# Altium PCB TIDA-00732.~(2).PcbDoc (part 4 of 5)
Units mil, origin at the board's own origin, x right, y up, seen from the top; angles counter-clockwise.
Board outline 8994.78 x 4186 mil, 6 copper layers (Top Layer, GND1, PWR1, PWR2, GND2, Bottom Layer), stack 97.668 mil thick; 693 components, 463 nets, 2087 pads, 616 vias.
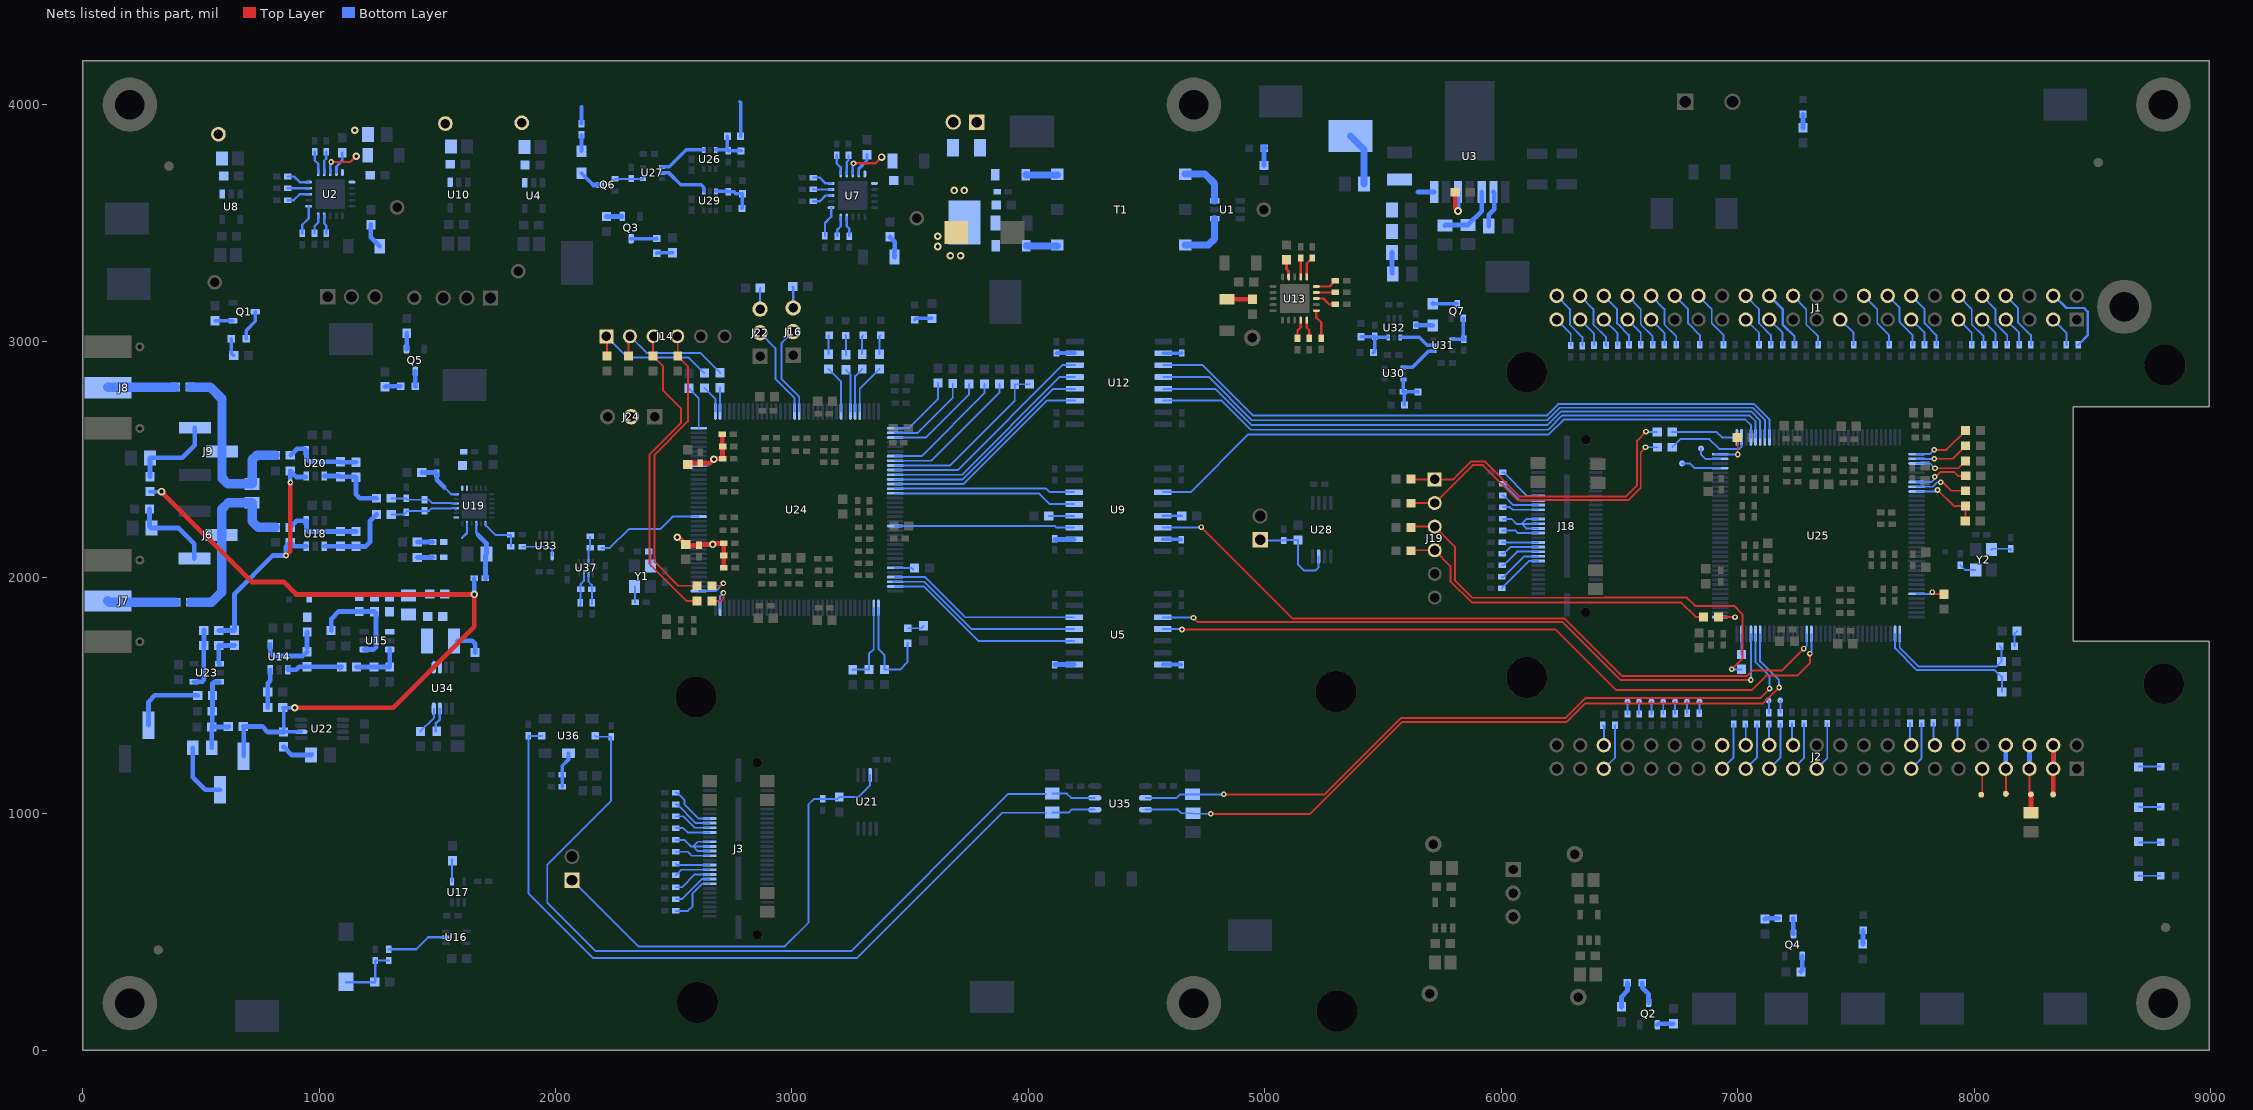
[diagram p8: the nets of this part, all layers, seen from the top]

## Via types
v1: diameter 32, hole 16, Top Layer to Bottom Layer, tented both sides, 393 vias
v2: diameter 24, hole 12, Top Layer to Bottom Layer, tented both sides, 174 vias
v3: diameter 19.68, hole 7.87, Top Layer to Bottom Layer, tented both sides, 20 vias
v4: diameter 40, hole 20, Top Layer to Bottom Layer, tented both sides, 19 vias
v5: diameter 36, hole 16, Top Layer to Bottom Layer, tented both sides, 9 vias
v6: diameter 24, hole 12, Top Layer to Bottom Layer, 1 vias

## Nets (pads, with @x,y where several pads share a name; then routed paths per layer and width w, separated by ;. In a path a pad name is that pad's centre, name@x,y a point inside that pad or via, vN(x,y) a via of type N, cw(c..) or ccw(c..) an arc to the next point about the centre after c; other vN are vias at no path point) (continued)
GPIO_38: J1.3 R1.2 | length 130.6
  Bottom Layer w8: J1.3@8334,3091 8390,3035 R1.2@8390,2983.62
GPIO_39: J1.4 R2.1 | length 330.7
  Bottom Layer w10: J1.4@8334,3191 8339,3191 8390,3140 8464.01,3140 8480,3124.01 8480,3023.62 R2.1@8440,2983.62
GPIO_46: J1.16 R14.1 | length 251.3
  Bottom Layer w8: J1.16@7734,3191 7790,3135 7790,3075 7840,3025 R14.1@7840,2983.62
GPIO_47: J1.15 R13.2 | length 130.6
  Bottom Layer w8: J1.15@7734,3091 7790,3035 R13.2@7790,2983.62
GPIO_48: J2.15 R127.2 | length 210.4
  Bottom Layer w8: J2.15@7734,1191 7777.5,1234.5 R127.2@7777.5,1383.38
GPIO_49: J2.23 R135.2 | length 209.8
  Bottom Layer w8: J2.23@7334,1191 7378.5,1235.5 R135.2@7378.5,1382.38
GPIO_50: J2.14 R126.1 | length 97.1
  Bottom Layer w8: R126.1@7827.5,1385.38 7827.5,1297.5 J2.14@7834,1291
GPIO_51: J2.16 R128.1 | length 95.7
  Bottom Layer w8: R128.1@7728.5,1384.38 7728.5,1296.5 J2.16@7734,1291
GPIO_60: J2.12 R124.1 | length 96.2
  Bottom Layer w8: R124.1@7929.5,1385.38 7929.5,1295.5 J2.12@7934,1291
GPIO_61: J1.26 R24.1 | length 251.3
  Bottom Layer w8: J1.26@7234,3191 7290,3135 7290,3070 7340,3020 R24.1@7340,2983.62
GPIO_65: J1.18 R16.1 | length 251.3
  Bottom Layer w8: J1.18@7634,3191 7685,3140 7685,3080 7740,3025 R16.1@7740,2983.62
GPIO_66: J1.7 R5.2 | length 130.6
  Bottom Layer w8: J1.7@8134,3091 8190,3035 R5.2@8190,2983.62
GPIO_67: J1.8 R6.1 | length 251.3
  Bottom Layer w8: J1.8@8134,3191 8185,3140 8185,3080 8240,3025 R6.1@8240,2983.62
GPIO_68: J1.10 R8.1 | length 251.3
  Bottom Layer w8: J1.10@8034,3191 8090,3135 8090,3075 8140,3025 R8.1@8140,2983.62
GPIO_69: J1.9 R7.2 | length 130.6
  Bottom Layer w8: J1.9@8034,3091 8090,3035 R7.2@8090,2983.62
GPIO_78: J1.37 R35.2 | length 130.6
  Bottom Layer w8: J1.37@6634,3091 6690,3035 R35.2@6690,2983.62
GPIO_79: J1.38 R36.1 | length 251.3
  Bottom Layer w8: J1.38@6634,3191 6690,3135 6690,3070 6740,3020 R36.1@6740,2983.62
GPIO_80: J1.36 R34.1 | length 251.3
  Bottom Layer w8: J1.36@6734,3191 6790,3135 6790,3075 6840,3025 R34.1@6840,2983.62
GPIO_81: J1.34 R32.1 | length 251.3
  Bottom Layer w8: J1.34@6834,3191 6890,3135 6890,3075 6940,3025 R32.1@6940,2983.62
ISO_ADC_CONVST: U5.12 U24.71 | length 853
  Bottom Layer w8: U24.71@3436.35,1962.2 3557.8,1962.2 3788.01,1731.99 U5.12@4194,1731.99
ISO_ADC_CSN: U9.13 U24.51 | length 776.2
  Bottom Layer w8: U24.51@3436.35,2355.9 4044.1,2355.9 4089.02,2310.98 U9.13@4193.99,2310.98
ISO_ADC_RESETN: U5.14 U24.69 | length 827.9
  Bottom Layer w8: U24.69@3436.35,2001.57 3563.43,2001.57 3733.01,1831.99 U5.14@4194,1831.99
ISO_ADC_RVS: U9.11 U24.58 | length 760.6
  Bottom Layer w8: U24.58@3436.35,2218.1 4110.9,2218.1 4118.02,2210.98 U9.11@4193.99,2210.98
ISO_ADC_SCLK: U5.13 U24.70 | length 859.1
  Bottom Layer w8: U24.70@3436.35,1979.8 3429.53,1979.8 3427.45,1981.88 U24.70@3436.35,1981.88 3560.32,1981.88 3760.21,1781.99 U5.13@4194,1781.99
ISO_ADC_SDI: U9.14 U24.50 | length 763.7
  Bottom Layer w8: U24.50@3436.35,2375.58 4075.4,2375.58 4090,2360.98 U9.14@4193.99,2360.98
ISO_ADC_SDO0: U12.6 U24.46 | length 944.4
  Bottom Layer w8: U24.46@3436.35,2454.32 3700.32,2454.32 4144,2898 U12.6@4196.99,2898
ISO_ADC_SDO1: U12.3 U24.49 | length 906.7
  Bottom Layer w8: U24.49@3436.35,2395.27 3724.88,2395.27 4077.61,2748 U12.3@4196.99,2748
ISO_ADC_SDO2: U12.4 U24.48 | length 919.3
  Bottom Layer w8: U24.48@3436.35,2414.95 3722.36,2414.95 4105.41,2798 U12.4@4196.99,2798
ISO_ADC_SDO3: U12.5 U24.47 | length 931.9
  Bottom Layer w8: U24.47@3436.35,2434.64 3719.84,2434.64 4133.2,2848 U12.5@4196.99,2848
ISO_SCL: R206.1 R271.1 U35.6 U36.8 | length 3465.5
  Bottom Layer w8: R271.1@1885,1331.38 1885,665 2160,390 3275,390 3890,1005 R206.1@4075,1005 ; R271.1@1886.38,1330 U36.8@1942.2,1330 ; R206.1@4101,1006 4170,1006 4182,1018 U35.6@4280.72,1018
ISO_SDA: R204.1 R270.1 U35.7 U36.7 | length 3539.5
  Bottom Layer w8: U36.7@2167.8,1330 2171.42,1326.38 R270.1@2235,1326.38 2235,1055 1965,785 1965,625 2170,420 3250,420 3915,1085 R204.1@4075,1085 ; R204.1@4101,1086 4163,1086 4181,1068 U35.7@4280.72,1068
LDO_EN1: Q6.1 R250.2 U27.4 | length 118.2
  Bottom Layer w8: Q6.1@2251.5,3685.59 2321.79,3685.59 2321.97,3685.41 U27.4@2369.65,3685.41
LDO_EN2: Q7.1 R257.2 U31.4 | length 135.1
  Bottom Layer w15: U31.4@5794.35,3007.59 R257.2@5841,3007.62 ; R257.2@5839.59,3009.03 Q7.1@5839.59,3095.5
  Bottom Layer w20: R257.2@5839.59,3009.03 R257.2@5841,3007.62
LDO_IN_ISO: C4.1 C5.1 C7.1 C17.1 C18.1 C19.1 C20.1 C31.1 C32.1 C35.1 C36.1 J25.2 R51.2 R247.2 R248.2 TP8.1 TP13.1 TP14.1 U2.13 U2.15 U2.16 U4.1 U7.13 U7.15 U7.16 U8.1 U10.1 | length 566.2
  Top Layer w10: v2(1051,3757) 1132,3757 v1(1157,3782) ; v2(3260.66,3751.54) 3352.54,3751.54 v1(3379,3778)
  Top Layer w20: v1(1157,3782) v1@1160.92,3785.92
  Bottom Layer w10: U2.13@1047.52,3712.46 1047.52,3753.52 v2(1051,3757) ; U7.13@3257.18,3707 3257.18,3748.06 v2(3260.66,3751.54)
  Bottom Layer w15: R247.2@2110,3919.62 2110,3990 2111,3991 ; 2780,4012 2783,4009 R248.2@2783,3866
  Bottom Layer w20: v1(1151,3892) v1@1155,3892
MCLK: R273.2 U24.125 | length 466.9
  Bottom Layer w8: R273.2@2193.62,2125 2230,2125 2310,2205 2442.53,2205 2495,2257.47 U24.125@2605.65,2257.47
MODE_SW0: J16.2 U24.19 | length 389.8
  Bottom Layer w8: J16.2@3005,3040 2955,2990 2955,2840 3030.84,2764.16 U24.19@3030.84,2702.35
MODE_SW1: J22.2 U24.18 | length 393.2
  Bottom Layer w8: J22.2@2865,3035 2930,2970 2930,2840 3011.16,2758.84 U24.18@3011.16,2702.35
NetC1_1: C1.1 R46.1 | length 118
  Bottom Layer w20: C1.1@1585.88,1732.4 1647.6,1732.4 1660,1720 R46.1@1660,1682.5 R46.1@1659.09,1683.4
NetC2_1: C2.1 C3.2 C6.1 C237.1 D1.1 D3.1 J25.1 R51.1 TP3.1
  other v1: 3670,3361 3713,3361 3617,3400 3617,3443 3686,3637 3729,3637
NetC9_1: C9.1 R52.1 | length 107.2
  Bottom Layer w20: R52.1@1219,3492.5 1219,3438.93 C9.1@1256.93,3401
NetC10_2: C10.2 U2.14 | length 94.4
  Bottom Layer w12: U2.14@1073.11,3712.46 1073.11,3738.11 1098,3763 C10.2@1098,3796.5
NetC23_1: C23.1 R63.1 | length 94.5
  Bottom Layer w20: R63.1@3414,3440.5 3434.82,3419.68 3434.82,3390.39 3433.93,3389.5 C23.1@3433.93,3355
NetC24_2: C24.2 U7.14 | length 95.2
  Bottom Layer w12: U7.14@3282.77,3707 3282.77,3728.77 3317.18,3763.18 C24.2@3317.18,3787.97
NetC41_1: C41.1 U3.5 | length 164.1
  Top Layer w20: C41.1@5805.5,3629 5805.5,3563.5 5817,3552 v1(5817,3550)
  Bottom Layer w20: v1(5817,3550) U3.5@5817,3630.37
NetC42_1: C42.1 C91.1 L2.1 R220.2 TP32.1 U3.7 | length 296
  Bottom Layer w20: 5646.63,3630.37 U3.7@5717,3630.37
  Bottom Layer w30: TP32.1@5362,3867 5419,3810 L2.1@5419,3665
NetC47_1: C47.1 R76.1 | length 108.2
  Top Layer w15: C47.1@4839.25,3177.23 C47.1@4839.68,3176.8
  Top Layer w20: C47.1@4839.68,3176.8 R76.1@4947.25,3176.8
NetC48_2: C48.2 U13.14 | length 75.9
  Top Layer w12: C48.2@5091.25,3343.27 5091.25,3304.9 5100.66,3295.49 U13.14@5100.66,3271.3
NetC52_2: C52.2 R89.1 U15.1
NetC53_1: C53.1 R85.2 U14.3 | length 164
  Bottom Layer w20: R85.2@783.5,1450 C53.1@783.5,1515 783.5,1553.5 793.6,1563.6 U14.3@793.6,1609.87
NetC54_1: C54.1 R86.2 R88.2 U15.3 | length 214.9
  Bottom Layer w20: R86.2@1158.5,1622 1159,1621.5 R88.2@1233,1621.5 C54.1@1299,1621.5 1299.13,1621.63 U15.3@1299.13,1695.6
NetC56_1: C56.1 R87.1 R90.1 S1.2 | length 270
  Bottom Layer w10: S1.2@1114.33,289.43 1115.03,288.73 C56.1@1235.63,288.73 1238.13,291.23 R87.1@1238.13,380.11 R90.1@1294.13,380.11
NetC57_1: C57.1 R276.1 | length 64.9
  Bottom Layer w20: C57.1@1415.5,2085 R276.1@1480.38,2085
NetC58_1: C58.1 R268.1 | length 64.9
  Bottom Layer w20: C58.1@1415.5,2150 R268.1@1480.38,2150
NetC60_1: C60.1 R86.1 U14.1 | length 249.9
  Bottom Layer w20: U14.1@868.4,1619.4 U14.1@868.4,1609.87 904,1609.87 916.64,1622.5 C60.1@949,1622.5 949.5,1622 R86.1@1095.5,1622 R86.1@1090.01,1616.5
NetC60_2: C60.2 R94.1 U14.4 | length 273.9
  Bottom Layer w20: U14.4@793.6,1718.13 793.6,1680.4 806,1668 931.5,1668 C60.2@949,1685.5 ; C60.2@949,1701.5 949,1768.5 R94.1@950,1769.5
NetC61_2: C61.2 R91.2 R92.1 U15.4 | length 452.8
  Bottom Layer w20: R91.2@1051,1775.5 1051,1824 1083.5,1856.5 C61.2@1170,1856.5 1233,1856.5 R92.1@1234,1855.5 1241,1848.5 1241,1705 1231.6,1695.6 U15.4@1190.87,1695.6
NetC62_1: C62.1 R208.2 U19.13 U19.14
NetC66_1: C66.1 C214.1 R95.2 U19.9 | length 285.9
  Bottom Layer w8: R95.2@1305.5,2266 1357.38,2266 C66.1@1368,2276.62 1372.76,2281.38 C214.1@1446,2281.38 1464.81,2281.38 1474.93,2291.5 1559.73,2291.5 1561.39,2293.16 U19.9@1580.2,2293.16
NetC67_1: C67.1 R95.1 R99.2 U18.1 | length 328.8
  Bottom Layer w8: R99.2@1089.64,2131.87 R99.2@1090,2131.5
  Bottom Layer w20: U18.1@1021.4,2131.87 R99.2@1089.64,2131.87 ; R99.2@1090,2131.5 C67.1@1156,2131.5 1196.5,2131.5 1215,2150 1215,2238.5 R95.1@1242.5,2266
NetC67_2: C67.2 R98.2 R99.1 U18.4 | length 329.6
  Bottom Layer w20: R98.2@878.5,2212 906.63,2240.13 U18.4@946.6,2240.13 946.6,2203.4 955.5,2194.5 1025,2194.5 C67.2@1156,2194.5
NetC68_1: C68.1 J9.2 R103.2 R104.1 | length 834.9
  Bottom Layer w40: R103.2@455.5,2805 540,2805 589.5,2755.5 J9.2@589.5,2533 589.5,2420.5 614,2396 C68.1@717,2396 717,2497 737,2517 R104.1@815.5,2517
NetC68_2: C68.2 J6.2 R97.2 R98.1 | length 827.2
  Bottom Layer w40: R97.2@456.5,1895 545,1895 587.5,1937.5 J6.2@587.5,2180 587.5,2287.5 616,2316 C68.2@717,2316 717,2238 743,2212 R98.1@815.5,2212
NetC69_1: C69.1 R100.2 U19.3 | length 258.1
  Bottom Layer w10: U19.3@1664.84,2228.2 1664.84,2188.16 1673.5,2179.5
  Bottom Layer w20: 1673.5,2179.5 1708,2145 C69.1@1708,2099 1703.62,2094.62 R100.2@1703.62,1996 R100.2@1708,2000.38
NetC71_1: C71.1 C214.2 R101.2 U19.10 | length 283.9
  Bottom Layer w8: R101.2@1305.5,2335 1306.12,2334.38 C71.1@1369,2334.38 1374.76,2328.62 C214.2@1446,2328.62 1464.81,2328.62 1478.93,2314.5 1559.73,2314.5 1561.39,2312.84 U19.10@1580.2,2312.84
NetC72_1: C72.1 R102.1 U19.12 | length 200.3
  Bottom Layer w8: 1530,2381 1558.79,2352.21
  Bottom Layer w10: 1558.79,2352.21 U19.12@1580.2,2352.21
  Bottom Layer w20: C72.1@1434.5,2444 1495.38,2444 R102.1@1498,2441.38 1498,2413 1530,2381
NetC73_1: C73.1 R101.1 R105.2 U20.1 | length 302.5
  Bottom Layer w10: R105.2@1087.64,2428.87 R105.2@1090,2426.5 ; C73.1@1154,2426.5 C73.1@1156,2424.5
  Bottom Layer w20: U20.1@1021.4,2428.87 R105.2@1087.64,2428.87 ; R105.2@1090,2426.5 C73.1@1154,2426.5 ; C73.1@1156,2424.5 1156,2352 1173,2335 R101.1@1242.5,2335
NetC73_2: C73.2 R104.2 R105.1 U20.4 | length 332
  Bottom Layer w8: R104.2@878.5,2517 R104.2@879.78,2517 ; U20.4@939.53,2544.2 U20.4@946.6,2537.13 ; R105.1@1090,2489.5 R105.1@1092,2487.5
  Bottom Layer w20: R104.2@879.78,2517 906.98,2544.2 U20.4@939.53,2544.2 ; U20.4@946.6,2537.13 946.6,2503.4 960.5,2489.5 R105.1@1090,2489.5 ; R105.1@1092,2487.5 C73.2@1156,2487.5
NetC74_1: C74.1 R110.1 U23.1 | length 146.2
  Bottom Layer w20: U23.1@579.13,1634.42 575.5,1638.06 C74.1@575.5,1712.02 640.52,1712.02 R110.1@642,1713.5
NetC74_2: C74.2 R106.1 U23.4 | length 255.5
  Bottom Layer w20: U23.4@470.87,1559.62 505.6,1559.62 512.5,1566.53 C74.2@512.5,1712.02 ; C74.2@513,1712.02 R106.1@513,1777.53
NetC80_1: C80.1 R109.2 R111.2 R112.2 R114.2 U23.3 | length 377.6
  Bottom Layer w20: R109.2@546,1280 546.5,1280.5 R114.2@546.5,1368.02 ; U23.3@579.13,1559.62 556.28,1559.62 549.5,1552.83 R112.2@549.5,1501.02 549.5,1435.02 C80.1@548.5,1434.02 548.5,1370.02 R114.2@546.5,1368.02 ; R111.2@616.5,1370 614.53,1368.02 R114.2@546.5,1368.02
NetC81_1: C81.1 R113.1 | length 136.7
  Bottom Layer w15: C81.1@966,1249 C81.1@970.5,1253.5
  Bottom Layer w20: R113.1@850,1283.5 884.5,1249 C81.1@966,1249
NetC150_1: C150.1 R248.1 R249.2 U26.3 | length 167.6
  Bottom Layer w15: U26.3@2677.59,3808.35 2726.27,3808.35 C150.1@2727,3807.62 ; R248.1@2727,3866 C150.1@2727,3807.62 ; R249.2@2785,3804 2784.38,3804.62 C150.1@2730,3804.62 C150.1@2727,3807.62
NetC197_1: C197.1 U34.4 | length 119.4
  Bottom Layer w8: C197.1@1428.8,1348.9 1485.41,1405.51 U34.4@1485.41,1444.8
NetC221_1: C221.1 R252.1 R253.2 U29.3 | length 178.5
  Bottom Layer w15: U29.3@2678.59,3633.35 2729.02,3633.35 C221.1@2730,3632.38 2753.62,3632.38 2763,3623 R253.2@2790,3623 2790,3563 R252.1@2788,3561
NetC225_1: C225.1 R255.1 R256.2 U30.3 | length 171.3
  Bottom Layer w15: U30.3@5586.35,2837.41 5586.35,2785.73 C225.1@5585.62,2785 ; R256.2@5590,2730 5590,2780.62 C225.1@5585.62,2785 ; R255.1@5647,2784 5646,2785 C225.1@5585.62,2785
NetC227_1: C227.1 R258.1 R259.2 U32.3 | length 188.8
  Bottom Layer w15: R259.2@5407,3018 5461.62,3018 C227.1@5464,3020.38 ; R258.1@5459,2951 5464,2956 C227.1@5464,3020.38 ; U32.3@5521.41,3015.65 5468.73,3015.65 C227.1@5464,3020.38
NetC234_2: C234.2 R274.2 U37.3 | length 138.6
  Bottom Layer w8: C234.2@2105,1893.62 C234.2@2106.38,1895 ; C234.2@2106.38,1882.87 C234.2@2106.38,1895 ; U37.3@2119.8,2013.94 2119.8,1985.3 2106.38,1971.88 R274.2@2106.38,1950 C234.2@2106.38,1895
NetC235_2: C235.2 R274.1 U37.2 | length 131.9
  Bottom Layer w8: U37.2@2139.49,2013.94 2139.49,1982.17 2153.62,1968.03 R274.1@2153.62,1950 C235.2@2153.62,1887.87
NetD1_2: D1.2 T1.6 | length 133.7
  Bottom Layer w30: D1.2@3989.47,3704 3990.99,3702.48 T1.6@4122.53,3702.48
NetD3_2: D3.2 T1.4 | length 131.3
  Bottom Layer w30: D3.2@3991.47,3403 3991.99,3402.48 T1.4@4122.53,3402.48
NetD5_1: D5.1 R168.2 | length 71.1
  Bottom Layer w8: D5.1@3490,1785.5 3547,1785.5 R168.2@3557,1795.5
NetD6_1: D6.1 R187.2 | length 68.6
  Bottom Layer w8: D6.1@8170.5,1709 8170.5,1762 R187.2@8181.5,1773
NetD7_2: D7.2 R222.1 | length 74.1
  Bottom Layer w20: R222.1@4996,3742.5 D7.2@4996,3814.5
  Bottom Layer w30: D7.2@4996,3814.5 D7.2@4997.5,3816
NetD8_2: D8.2 R226.1 | length 57
  Bottom Layer w20: R226.1@7276,3901.5 D8.2@7276,3958.5
NetD9_1: D9.1 R227.2 | length 82.4
  Bottom Layer w8: D9.1@3227,3023.5 3228,3022.5 R227.2@3228,2941.5
NetD10_1: D10.1 R228.2 | length 80.8
  Bottom Layer w8: R228.2@3155,2944.5 3155,3022.5 D10.1@3157,3024.5
NetD11_1: D11.1 R229.2 | length 82.1
  Bottom Layer w8: R229.2@3370,2944.5 3370,3019.5 D11.1@3375,3024.5
NetD12_1: D12.1 R230.2 | length 81.7
  Bottom Layer w8: R230.2@3297,2944.5 3297,3020.5 D12.1@3301,3024.5
NetD13_2: D13.2 R231.1 | length 75.5
  Bottom Layer w15: D13.2@3519,3089.5 3525,3095.5 R231.1@3592,3095.5
NetD14_2: D14.2 R232.1 | length 59.4
  Bottom Layer w20: R232.1@7529,449.5 7530,450.5 D14.2@7530,508.5
NetD15_1: D15.1 Q1.3 | length 131
  Bottom Layer w15: D15.1@691.5,3009 691.5,3044.5 730.24,3083.24 Q1.3@730.24,3124
NetD15_2: D15.2 R233.1 | length 74.1
  Bottom Layer w15: D15.2@628.5,3009 628.5,2949 R233.1@638.5,2939
NetD16_1: D16.1 Q2.3 | length 94.7
  Bottom Layer w20: D16.1@6596.36,286.37 6596.36,264.87 6622.87,238.37 Q2.3@6622.87,202.61
NetD16_2: D16.2 R235.1 | length 112.7
  Bottom Layer w20: R235.1@6508.87,183.87 6508.87,227.37 6533.37,251.87 D16.2@6533.37,286.37
NetD17_1: D17.1 Q3.3 | length 110.5
  Bottom Layer w15: Q3.3@2317.56,3432.49 2426.31,3432.49 D17.1@2427.56,3433.74
NetD17_2: D17.2 R236.1 | length 68.6
  Bottom Layer w15: D17.2@2427.56,3370.75 2430.32,3373.5 R236.1@2495,3373.5
NetD18_1: D18.1 Q4.3 | length 66
  Bottom Layer w20: D18.1@7235.28,559.03 7235.28,493.78 Q4.3@7235.78,493.28
NetD18_2: D18.2 R239.1 | length 58
  Bottom Layer w20: R239.1@7115.78,555.53 7119.29,559.03 D18.2@7172.29,559.03
NetD19_1: D19.1 Q5.3 | length 63
  Bottom Layer w20: Q5.3@1407,2871.76 1407,2809.5 D19.1@1407.5,2809
NetD19_2: D19.2 R240.1 | length 66.5
  Bottom Layer w20: R240.1@1279,2806.5 1281.5,2809 D19.2@1344.5,2809
NetD20_1: D20.1 R247.1 | length 70.1
  Bottom Layer w15: D20.1@2110,3802.26 R247.1@2110,3872.38
NetD20_2: D20.2 Q6.3 | length 99.1
  Bottom Layer w15: D20.2@2110,3709.74 2159.74,3660
  Bottom Layer w20: 2159.74,3660 Q6.3@2188.5,3660
NetD21_1: D21.1 R254.1 | length 72.7
  Bottom Layer w20: R254.1@5638,3067.38 5708.36,3067.38 D21.1@5710,3065.74
NetD21_2: D21.2 Q7.3 | length 104.1
  Bottom Layer w15: D21.2@5710.24,3158.5 Q7.3@5814,3158.5
  Bottom Layer w20: D21.2@5710,3158.26 D21.2@5710.24,3158.5
NetD22_1: D22.1 R209.2 | length 92
  Bottom Layer w8: R209.2@8696.5,1200 D22.1@8788.5,1200
NetD23_1: D23.1 R264.2 | length 92
  Bottom Layer w8: R264.2@8696.5,1030 D23.1@8788.5,1030
NetD24_1: D24.1 R265.2 | length 94.1
  Bottom Layer w8: R265.2@8695,737.01 8696.5,738.5 D24.1@8788.5,738.5
NetD25_1: D25.1 R266.2 | length 90
  Bottom Layer w8: R266.2@8698.5,880 D25.1@8788.5,880
NetJ3_16: J3.16 R160.2 | length 223
  Bottom Layer w8: R160.2@2508.62,590 2560,590 2580,610 2580,663.79 2621.15,704.94 J3.16@2652.5,704.94
NetJ3_18: J3.18 R162.2 | length 178.9
  Bottom Layer w8: R162.2@2508.62,640 2534.01,640 2618.65,724.64 J3.18@2652.5,724.64
NetJ3_20: J3.20 R163.2 | length 166.4
  Bottom Layer w8: R163.2@2508.62,690 2535,690 2589.34,744.34 J3.20@2652.5,744.34
NetJ3_22: J3.22 R164.2 | length 153.8
  Bottom Layer w8: R164.2@2508.62,740 2532.67,764.04 J3.22@2652.5,764.04
NetJ3_24: J3.24 R166.2 | length 146.5
  Bottom Layer w8: R166.2@2508.62,790 2514.88,783.74 J3.24@2652.5,783.74
NetJ3_28: J3.28 R169.2 | length 150.9
  Bottom Layer w8: R169.2@2508.62,840 2560,840 2576.86,823.14 J3.28@2652.5,823.14
NetJ3_30: J3.30 J3.32 J3.34 R170.2 | length 311.7
  Bottom Layer w8: R170.2@2508.62,890 2545,890 2572.46,862.54 2582.46,862.54 ; J3.30@2652.5,842.84 2602.16,842.84 2582.46,862.54 ; J3.32@2652.5,862.54 2582.46,862.54 ; J3.34@2652.5,882.24 2602.16,882.24 2582.46,862.54
NetJ3_38: J3.38 R171.2 | length 151.5
  Bottom Layer w8: R171.2@2508.62,940 2540,940 2558.36,921.64 J3.38@2652.5,921.64
NetJ3_40: J3.40 R172.2 | length 164
  Bottom Layer w8: R172.2@2508.62,990 2540,990 2588.66,941.34 J3.40@2652.5,941.34
NetJ3_42: J3.42 R173.2 | length 176.6
  Bottom Layer w8: R173.2@2508.62,1040 2515,1040 2593.96,961.04 J3.42@2652.5,961.04
NetJ3_44: J3.44 R175.2 | length 200.8
  Bottom Layer w8: R175.2@2508.62,1090 2515,1090 2545,1060 2545,1040 2604.26,980.74 J3.44@2652.5,980.74
NetJ10_2: J10.2 R109.1 | length 261.9
  Bottom Layer w20: R109.1@466,1280 466,1155 518.87,1102.13 J10.2@581,1102.13
NetJ11_1: J11.1 R112.1 | length 318.1
  Bottom Layer w20: J11.1@279,1375.89 279,1475.02 305.87,1501.89 485.64,1501.89 R112.1@486.5,1501.02
NetJ16_3: J16.3 R107.1 | length 90.6
  Bottom Layer w10: R107.1@3003.5,3230 3005,3228.5 J16.3@3005,3140
NetJ18_16: J18.16 R186.2 | length 201.7
  Bottom Layer w8: R186.2@6002.62,1953.8 6118.62,2069.8 J18.16@6156,2069.8 J18.16@6155.8,2070
NetJ18_18: J18.18 R189.2 | length 189.3
  Bottom Layer w8: R189.2@6002.62,2002.8 6009.8,2002.8 6096.5,2089.5 J18.18@6156,2089.5
NetJ18_20: J18.20 R190.2 | length 176.2
  Bottom Layer w8: R190.2@6003.62,2051.8 6009.8,2051.8 6067.2,2109.2 J18.20@6156,2109.2
NetJ18_22: J18.22 R193.2 | length 164
  Bottom Layer w8: R193.2@6003.62,2100.8 6010.8,2100.8 6038.9,2128.9 J18.22@6156,2128.9
NetJ18_24: J18.24 R195.2 | length 151.9
  Bottom Layer w8: R195.2@6004.62,2149.8 6005.82,2148.6 J18.24@6156,2148.6
NetJ18_28: J18.28 R199.2 | length 154.9
  Bottom Layer w8: R199.2@6005.62,2198.8 6058.2,2198.8 6069,2188 J18.28@6156,2188
NetJ18_30: J18.30 J18.32 J18.34 R200.2 | length 314.5
  Bottom Layer w8: R200.2@6006.62,2247.8 6043.2,2247.8 6064,2227 6086,2227 ; J18.30@6156,2207.7 6105.3,2207.7 6086,2227 ; J18.32@6156,2227.4 6155.6,2227 6086,2227 ; J18.34@6156,2247.1 6106.1,2247.1 6086,2227
NetJ18_38: J18.38 R210.2 | length 154.1
  Bottom Layer w8: R210.2@6006.62,2297.8 6036.2,2297.8 6047.5,2286.5 J18.38@6156,2286.5
NetJ18_40: J18.40 R212.2 | length 167.2
  Bottom Layer w8: R212.2@6005.62,2346.8 6010.2,2346.8 6050.8,2306.2 J18.40@6156,2306.2
NetJ18_42: J18.42 R213.2 | length 179.3
  Bottom Layer w8: R213.2@6005.62,2395.8 6009.2,2395.8 6079.1,2325.9 J18.42@6156,2325.9
NetJ18_44: J18.44 R215.2 | length 191.5
  Bottom Layer w8: R215.2@6005.62,2444.8 6009.5,2444.8 6108.7,2345.6 J18.44@6156,2345.6
NetJ22_3: J22.3 R243.1 | length 90.6
  Bottom Layer w8: J22.3@2865,3135 2865,3223.5 R243.1@2866.5,3225
NetQ1_1: Q1.1 R234.1 | length 75.8
  Bottom Layer w15: R234.1@560,3086.5 635.66,3086.5 Q1.1@635.76,3086.6
NetQ2_1: Q2.1 R237.1 | length 69.6
  Bottom Layer w20: Q2.1@6660.27,108.13 6665.02,112.87 R237.1@6727.87,112.87
NetQ3_1: Q3.1 R238.1 | length 67.9
  Bottom Layer w20: R238.1@2215,3526.5 2215.75,3527.24 Q3.1@2282.6,3527.24
NetQ4_1: Q4.1 R241.1 | length 69.2
  Bottom Layer w20: R241.1@7267.28,332.03 7273.18,337.94 Q4.1@7273.18,398.79
NetQ5_1: Q5.1 R242.1 | length 66.8
  Bottom Layer w20: Q5.1@1369.6,2966.24 1371,2967.65 R242.1@1371,3032.5
NetR45_1: R45.1 R261.1 U19.1 | length 181.5
  Bottom Layer w8: U19.1@1704.21,2228.2 1704.21,2220.79 1745,2180 R45.1@1811.38,2180 R261.1@1811.38,2130
NetR47_2: R47.2 U34.3 | length 103
  Bottom Layer w10: R47.2@1493.8,1348.9 1493.8,1382.8 1511,1400 U34.3@1511,1444.8
NetR53_2: R53.2 U2.4 | length 76.4
  Bottom Layer w10: U2.4@1021.93,3529.39 1021.93,3497.07 1030.52,3488.48 R53.2@1030.52,3456.54
NetR54_2: R54.2 U2.5 | length 79.4
  Bottom Layer w10: R54.2@980.52,3456.54 980.52,3485.52 996.34,3501.34 U2.5@996.34,3529.39
NetR55_2: R55.2 U2.6 | length 125.7
  Bottom Layer w10: R55.2@929.08,3455.14 929.08,3491.92 955.98,3518.83 U2.6@955.98,3569.74
NetR56_2: R56.2 U2.8 | length 98.2
  Bottom Layer w10: R56.2@868.14,3595.92 892.92,3595.92 917.92,3620.92 U2.8@955.98,3620.92
NetR57_2: R57.2 U2.9 | length 88.1
  Bottom Layer w10: R57.2@868.14,3645.92 868.73,3646.51 U2.9@955.98,3646.51
NetR58_2: R58.2 U2.10 | length 97.7
  Bottom Layer w10: R58.2@868.14,3695.92 894.08,3695.92 917.9,3672.1 U2.10@955.98,3672.1
NetR59_2: R59.2 U2.11 | length 94.7
  Bottom Layer w10: R59.2@981,3800.76 981,3765 996.34,3749.66 U2.11@996.34,3712.46
NetR60_2: R60.2 U2.12 | length 92.1
  Bottom Layer w10: U2.12@1021.93,3712.46 1021.93,3762.86 1031,3771.93 R60.2@1031,3800.76
NetR61_2: R61.2 U5.7 | length 78.6
  Bottom Layer w15: U5.7@4568.02,1631.99 4644.63,1631.99 R61.2@4646.01,1630.61
NetR62_1: R62.1 U5.10 | length 83.6
  Bottom Layer w20: R62.1@4111.01,1630.61 4112.39,1631.99 U5.10@4194,1631.99
NetR64_2: R64.2 U7.4 | length 84.2
  Bottom Layer w10: U7.4@3231.59,3523.93 3231.59,3486.05 3242.18,3475.46 R64.2@3242.18,3444.09
NetR65_2: R65.2 U7.5 | length 85.6
  Bottom Layer w10: R65.2@3192.18,3444.09 3192.18,3471.47 3206,3485.28 U7.5@3206,3523.93
NetR66_2: R66.2 U7.6 | length 130.3
  Bottom Layer w10: R66.2@3139.54,3444.8 3139.54,3499.54 3165.65,3525.65 U7.6@3165.65,3564.28
NetR67_2: R67.2 U7.8 | length 84.8
  Bottom Layer w10: R67.2@3090.8,3591.46 3118.18,3591.46 3142.18,3615.46 U7.8@3165.65,3615.46
NetR68_2: R68.2 U7.9 | length 75
  Bottom Layer w10: R68.2@3090.8,3641.46 3091.21,3641.06 U7.9@3165.65,3641.06
NetR69_2: R69.2 U7.10 | length 85.1
  Bottom Layer w10: R69.2@3090.8,3691.46 3117.18,3691.46 3142,3666.65 U7.10@3165.65,3666.65
NetR70_2: R70.2 U7.11 | length 86.2
  Bottom Layer w10: R70.2@3189.18,3786.22 3189.18,3751.46 3206,3734.65 U7.11@3206,3707
NetR71_2: R71.2 U7.12 | length 82.4
  Bottom Layer w10: U7.12@3231.59,3707 3231.59,3734.87 3231.59,3757.41 3239.18,3765 R71.2@3239.18,3786.22
NetR72_2: R72.2 U9.7 | length 78.6
  Bottom Layer w15: U9.7@4568.01,2160.98 4644.62,2160.98 R72.2@4646,2159.61
NetR73_1: R73.1 U9.10 | length 83.6
  Bottom Layer w20: R73.1@4111,2159.61 4112.38,2160.98 U9.10@4193.99,2160.98
NetR74_1: R74.1 U12.10 | length 78.6
  Bottom Layer w15: U12.10@4571.01,2948 4647.62,2948 R74.1@4649,2949.38
NetR75_2: R75.2 U12.7 | length 78.6
  Bottom Layer w15: R75.2@4119,2949.38 4195.61,2949.38 U12.7@4196.99,2948
NetR77_2: R77.2 U13.4 | length 83.3
  Top Layer w10: R77.2@5138.84,3011.98 R77.2@5138.25,3011.39 5138.25,3044.3 5151.84,3057.89 U13.4@5151.84,3088.23
NetR78_2: R78.2 U13.5 | length 81.3
  Top Layer w10: U13.5@5177.43,3088.23 5177.43,3056.12 5188.25,3045.3 R78.2@5188.25,3011.39
NetR79_2: R79.2 U13.6 | length 124.9
  Top Layer w10: U13.6@5217.78,3128.58 5217.78,3099.22 5238.76,3078.24 R79.2@5238.76,3012.37
NetR80_2: R80.2 U13.8 | length 90.8
  Top Layer w10: U13.8@5217.78,3179.76 5247.79,3179.76 5271.79,3155.76 R80.2@5298.63,3155.76
NetR81_2: R81.2 U13.9 | length 81
  Top Layer w10: U13.9@5217.78,3205.35 5298.22,3205.35 R81.2@5298.63,3205.76
NetR82_2: R82.2 U13.10 | length 91.1
  Top Layer w10: U13.10@5217.78,3230.94 5273.81,3230.94 R82.2@5298.63,3255.76
NetR83_2: R83.2 U13.11 | length 89.7
  Top Layer w10: U13.11@5177.43,3271.3 5177.43,3327.32 R83.2@5201.25,3351.14
NetR84_2: R84.2 U13.12 | length 80.1
  Top Layer w8: R84.2@5151.25,3351.14 R84.2@5151.84,3350.55
  Top Layer w10: U13.12@5151.84,3271.3 R84.2@5151.84,3350.55
NetR90_2: R90.2 U16.2 | length 262.8
  Bottom Layer w10: R90.2@1294.13,427.35 1411.25,427.35 1462.13,478.23 U16.2@1535.84,478.23
NetR115_2: R115.2 U24.2 | length 100.2
  Bottom Layer w8: R115.2@2696,2802.5 2696.2,2802.31 U24.2@2696.2,2702.35
NetR116_2: R116.2 U24.107 | length 146.7
  Top Layer w8: R116.2@2661.5,1900 2700,1900 2710,1910 v2(2710,1935)
  Bottom Layer w8: U24.107@2696.2,1871.65 2696.2,1921.2 v2(2710,1935)
NetR117_2: R117.2 U24.109 | length 170.5
  Top Layer w8: R117.2@2661.5,1965 2700,1965 v2(2710,1975)
  Bottom Layer w8: U24.109@2605.65,1942.51 2677.51,1942.51 v2(2710,1975)
NetR118_2: R118.2 U24.1 | length 118.4
  Bottom Layer w8: R118.2@2630,2801.5 2676.51,2754.99 U24.1@2676.51,2702.35
NetR139_1: R139.1 TP51.1 | length 51.6
  Bottom Layer w8: TP51.1@7180,1480 7180.5,1479.5 R139.1@7180.5,1428.62
NetR140_2: R140.2 TP50.1 | length 53
  Bottom Layer w8: TP50.1@7130,1480 7131.5,1478.5 R140.2@7131.5,1427.62
NetR144_1: R144.1 TP21.1 | length 49.4
  Bottom Layer w8: R144.1@6838,1425.62 TP21.1@6838,1475
NetR145_1: R145.1 TP20.1 | length 49.8
  Bottom Layer w8: TP20.1@6785,1475 6785,1426.62 R145.1@6786,1425.62
NetR146_2: R146.2 TP24.1 | length 51.4
  Bottom Layer w8: R146.2@6735,1423.62 TP24.1@6735,1475
NetR147_1: R147.1 TP19.1 | length 51.4
  Bottom Layer w8: R147.1@6685,1423.62 TP19.1@6685,1475
NetR148_2: R148.2 TP23.1 | length 52.4
  Bottom Layer w8: R148.2@6635,1422.62 TP23.1@6635,1475
NetR149_1: R149.1 TP18.1 | length 52.4
  Bottom Layer w8: R149.1@6583,1422.62 TP18.1@6583,1475
NetR150_2: R150.2 TP22.1 | length 52.4
  Bottom Layer w8: R150.2@6534,1422.62 TP22.1@6534,1475
NetR161_1: R161.1 Y1.1 | length 67.1
  Bottom Layer w8: Y1.1@2334.18,1961.2 2336.38,1959.01 R161.1@2336.38,1895
NetR167_1: R167.1 Y1.3 | length 72.3
  Bottom Layer w8: R167.1@2397.14,2118.51 2401.11,2114.54 Y1.3@2401.11,2047.82
NetR179_1: R179.1 Y2.1 | length 88.4
  Bottom Layer w8: Y2.1@8073.46,2118.31 8076.54,2121.38 R179.1@8155,2121.38 ; R179.1@8151.06,2117.44 R179.1@8155,2113.5
NetR180_1: R180.1 Y2.3 | length 74.1
  Bottom Layer w8: R180.1@7941,2052.38 7961.69,2031.69 Y2.3@8006.54,2031.69
NetR192_2: R192.2 U25.2 | length 366.6
  Bottom Layer w8: R192.2@6723.5,2551 6757.5,2585 6880,2585 6921,2544 7006.76,2544 7016.2,2553.43 U25.2@7016.2,2592.35
NetR194_2: R194.2 U25.107 | length 87.2
  Bottom Layer w8: R194.2@7016,1674.5 7016.2,1674.69 U25.107@7016.2,1761.65
NetR197_2: R197.2 U25.109 | length 133
  Top Layer w8: R197.2@6918.5,1833 6918.98,1832.51 v2(6988.49,1832.51)
  Bottom Layer w8: U25.109@6925.65,1832.51 v2(6988.49,1832.51)
NetR198_2: R198.2 U25.1 | length 285.2
  Bottom Layer w8: R198.2@6723.5,2617 R198.2@6722.5,2616 6910,2616 6914,2612 6933.65,2592.35 U25.1@6996.51,2592.35
NetR207_1: R207.1 U9.12 | length 107.9
  Bottom Layer w8: R207.1@4086.5,2260 4193.01,2260 U9.12@4193.99,2260.98
NetR219_1: R219.1 R224.2 U3.3 | length 261.2
  Bottom Layer w20: R224.2@5762,3489 5764,3491 R219.1@5859,3491 5917,3549 U3.3@5917,3630.37
NetR221_1: R221.1 U3.2 | length 155.1
  Bottom Layer w20: R221.1@5947,3486 5947,3534 5970,3557 5970,3627.37 U3.2@5967,3630.37
NetR223_1: R223.1 R225.2 | length 92.2
  Bottom Layer w15: R225.2@5538,3287 R225.2@5541,3284
  Bottom Layer w20: R225.2@5538,3287 R223.1@5538,3375
NetR244_1: R244.1 U17.4 | length 95.2
  Bottom Layer w8: R244.1@1562,807.91 1562.54,807.37 R244.1@1562.54,802.5 ; U17.4@1562.54,713.52 1562.54,801.04 R244.1@1564,802.5
NetR260_2: R260.2 U9.5 | length 80.9
  Bottom Layer w10: U9.5@4568.01,2260.98 4647.52,2260.98 R260.2@4648.5,2260
NetR261_2: R261.2 U33.4 | length 156.6
  Bottom Layer w8: R261.2@1858.62,2130 1970,2130 1986.1,2113.9 U33.4@1986.1,2091.4
NetR267_2: R267.2 R277.2 U36.2@2055,1257.17 | length 153.1
  Bottom Layer w15: R277.2@2028.62,1115 R267.2@2028.62,1165 2028.62,1203.62 2055,1230 U36.2@2055,1257.17
NetR269_1: R269.1 R273.1 U37.8 | length 109.9
  Bottom Layer w8: U37.8@2139.49,2067.09 2139.49,2113.98 2146.02,2120.51 R269.1@2146.02,2170.51 ; R273.1@2139.49,2114.85 R273.1@2142.15,2117.51
NetT1_1: T1.1 U1.3 | length 213.6
  Bottom Layer w30: T1.1@4663.47,3706 4747,3706 4787.94,3665.06 U1.3@4787.94,3592.92
NetT1_3: T1.3 U1.1 | length 220.8
  Bottom Layer w30: T1.3@4663.47,3406 4761,3406 4787.94,3432.94 U1.1@4787.94,3518.12
NetTP33_1: TP33.1 U25.141 | length 180.3
  Bottom Layer w8: TP33.1@6772,2475 TP33.1@6764.43,2482.57 6797.43,2482.57 6817.57,2462.43 U25.141@6925.65,2462.43
NetTP34_1: TP34.1 U25.143 | length 113.2
  Bottom Layer w8: TP34.1@6845,2545 6845,2520 6863.2,2501.8 U25.143@6925.65,2501.8
NetU26_1: U26.1 U27.1 | length 205.8
  Bottom Layer w15: U27.1@2450.35,3736.59 2480.59,3736.59 2552.35,3808.35 U26.1@2626.41,3808.35
NetU27_2: U27.2 U29.1 | length 218.6
  Bottom Layer w15: U27.2@2450.35,3711 2480,3711 2530,3661 2615.72,3661 2627.41,3649.31 U29.1@2627.41,3633.35
NetU30_1: U30.1 U31.1 | length 155.4
  Bottom Layer w15: U30.1@5586.35,2888.59 5624.59,2888.59 5692.41,2956.41 U31.1@5713.65,2956.41
NetU31_2: U31.2 U32.1 | length 155
  Bottom Layer w15: U32.1@5572.59,3015.65 5653.35,3015.65 5687,2982 U31.2@5713.65,2982
NISO_SCL: R50.1 U25.103 U35.3 | length 3168.2
  Top Layer w8: v2@4771,1000 5192.2,1000 5581.5,1389.3 6276.5,1389.3 6353.5,1466.3 7106.3,1466.3 v2(7175,1535)
  Bottom Layer w8: U35.3@4495.28,1018 4632,1018 4647,1003 R50.1@4696,1003 4698,1001 v2(4771,1001) ; U25.103@7094.94,1761.65 7094.94,1645.06 7175,1565 v2(7175,1535)
NISO_SDA: R205.1 U25.104 U35.2 | length 3087.9
  Top Layer w8: v2@4826,1082 5252,1082 5575,1405 6270,1405 6355,1490 7095,1490 v2(7135,1530)
  Bottom Layer w8: U35.2@4495.28,1068 4627,1068 4642,1083 R205.1@4694,1083 v2(4826,1083) ; U25.104@7075.25,1761.65 7075.25,1642.54 7135,1582.8 v2(7135,1530)
OPA625_CM: C65.1 C70.1 R106.2 R110.2 U18.3 U20.3 | length 1100.4
  Top Layer w20: v2(860,2093) 878.5,2111.5 v2(878.5,2401.5)
  Bottom Layer w8: U20.3@942.73,2425 U20.3@946.6,2428.87
  Bottom Layer w10: U18.3@939.73,2125 U18.3@946.6,2131.87
  Bottom Layer w20: R106.2@575.5,1776 641.5,1776 R110.2@642,1776.5 642,1930 805,2093 v2(860,2093) 860,2130.5 C65.1@878.5,2149 895.63,2131.87 U18.3@946.6,2131.87 ; v2(878.5,2401.5) C70.1@878.5,2451 904.5,2425 U20.3@942.73,2425
PRU1_0: J1.45 R43.2 | length 134.6
  Bottom Layer w8: J1.45@6234,3091 6294,3031 R43.2@6294,2981.24
PRU1_1: J1.46 R44.1 | length 255.5
  Bottom Layer w8: J1.46@6234,3191 6290,3135 6290,3070 6343,3017 R44.1@6343,2980.62
PRU1_2: J1.43 R41.2 | length 132.4
  Bottom Layer w8: J1.43@6334,3091 6392,3033 R41.2@6392,2982.62
PRU1_3: J1.44 R42.1 | length 254.5
  Bottom Layer w8: J1.44@6334,3191 6390,3135 6390,3070 6443,3017 R42.1@6443,2981.62
PRU1_4: J1.41 R39.2 | length 132.4
  Bottom Layer w8: J1.41@6434,3091 6492,3033 R39.2@6492,2982.62
PRU1_5: J1.42 R40.1 | length 251.3
  Bottom Layer w8: J1.42@6434,3191 6490,3135 6490,3075 6540,3025 R40.1@6540,2983.62
PRU1_6: J1.39 R37.2 | length 130.6
  Bottom Layer w8: J1.39@6534,3091 6590,3035 R37.2@6590,2983.62
PRU1_7: J1.40 R38.1 | length 251.3
  Bottom Layer w8: J1.40@6534,3191 6590,3135 6590,3070 6640,3020 R38.1@6640,2983.62
PRU1_8: J1.27 R25.2 | length 130.6
  Bottom Layer w8: J1.27@7134,3091 7190,3035 R25.2@7190,2983.62
PRU1_9: J1.29 R27.2 | length 130.6
  Bottom Layer w8: J1.29@7034,3091 7090,3035 R27.2@7090,2983.62
PRU1_10: J1.28 R26.1 | length 251.3
  Bottom Layer w10: J1.28@7134,3191 7190,3135 7190,3070 7240,3020 R26.1@7240,2983.62
PRU1_11: J1.30 R28.1 | length 251.3
  Bottom Layer w8: J1.30@7034,3191 7090,3135 7090,3075 7140,3025 R28.1@7140,2983.62
PRU1_12: J1.21 R19.2 | length 130.6
  Bottom Layer w8: J1.21@7434,3091 7490,3035 R19.2@7490,2983.62
PRU1_13: J1.20 R18.1 | length 251.3
  Bottom Layer w8: J1.20@7534,3191 7590,3135 7590,3075 7640,3025 R18.1@7640,2983.62
PRU1_16_IN: J2.26 R138.1 | length 93.2
  Bottom Layer w8: R138.1@7229.5,1382.38 7229.5,1295.5 J2.26@7234,1291
PRUO_0: J2.31 R143.2 | length 209.5
  Bottom Layer w8: J2.31@6934,1191 6982.5,1239.5 R143.2@6982.5,1380.38
PRUO_1: J2.29 R141.2 | length 209.1
  Bottom Layer w8: J2.29@7034,1191 7081.5,1238.5 R141.2@7081.5,1380.38
PRUO_2: J2.30 R142.1 | length 90
  Bottom Layer w8: R142.1@7032.5,1380.38 7034,1378.88 J2.30@7034,1291
PRUO_3: J2.28 R140.1 | length 90.4
  Bottom Layer w8: R140.1@7131.5,1380.38 7131.5,1293.5 J2.28@7134,1291
PRUO_4: J2.42 R152.1 | length 85
  Bottom Layer w8: R152.1@6430,1374.38 6434,1370.38 J2.42@6434,1291
PRUO_5: J2.27 R139.2 | length 209.6
  Bottom Layer w8: J2.27@7134,1191 7180.5,1237.5 R139.2@7180.5,1381.38
PRUO_6: J2.41 R151.2 | length 202.8
  Bottom Layer w8: J2.41@6434,1191 6481,1238 R151.2@6481,1374.38
PRUO_7: J2.25 R137.2 | length 210.6
  Bottom Layer w8: J2.25@7234,1191 7280.5,1237.5 R137.2@7280.5,1382.38
PRUO_14_OUT: J1.12 R10.1 | length 251.3
  Bottom Layer w8: J1.12@7934,3191 7990,3135 7990,3070 8040,3020 R10.1@8040,2983.62
PRUO_15_OUT: J1.11 R9.2 | length 130.6
  Bottom Layer w8: J1.11@7934,3091 7990,3035 R9.2@7990,2983.62
PWR_BUT: J2.9 TP15.1 | length 111.7
  Top Layer w8: TP15.1@8030,1081 8034,1085 J2.9@8034,1191
REF5045_BUF: C52.1 C61.1 D4.2 R49.2 R89.2 R92.2 R94.2
REF6045_BUF: C1.2 R48.2 U34.5 U34.6
REFBUF: R48.1 R49.1 R268.2 R276.2 U19.5 U19.7 | length 68.7
  Bottom Layer w10: 1605,2168 1625.47,2188.47 U19.5@1625.47,2228.2
REFOUT: J10.1 R85.1 R100.1 R108.2 R111.1 R113.2 U22.6 | length 3195.7
  Top Layer w20: v1(333.5,2363.5) 716.01,1981 850,1981 902.62,1928.38 v1(1656.38,1928.38) 1656.38,1791.38 1314,1449 v1(897,1449)
  Bottom Layer w15: R108.2@285,2363.5 v1(333.5,2363.5) ; R113.2@850,1346.5 R113.2@850,1347.2 ; v1(897,1449) 896,1450 R85.1@846.5,1450 850,1446.5 R113.2@850,1347.2 ; U22.6@925.4,1347.2 R113.2@850,1347.2
  Bottom Layer w20: J10.1@681,1243.87 681,1368.5 R111.1@679.5,1370 759,1370 782.5,1346.5 R113.2@850,1346.5 ; v1(1656.38,1928.38) R100.1@1656.38,1996
RVS: U9.6 U25.93 | length 3091.8
  Top Layer w8: v2(4731,2213) 5116.9,1827.1 6266.71,1827.1 6510.81,1583 7038.48,1583 7061.48,1606 7186,1606 v2(7279,1699) v2@7281.7,1701.7
  Bottom Layer w8: U9.6@4568.01,2210.98 v2@4731,2210.98 ; v2(7279,1699) 7291.79,1711.79 U25.93@7291.79,1761.65
SCLK: U5.4 U25.92 | length 3017.4
  Top Layer w8: v2(4650,1780) 6230,1780 6486,1524 7059,1524 7120,1585 7252,1585 7305,1638 v2(7305,1678)
  Bottom Layer w8: U5.4@4568.02,1781.99 4648.01,1781.99 v2(4650,1780) ; v2(7305,1678) 7311.47,1684.47 U25.92@7311.47,1761.65
SDI: U9.3 U25.4 | length 2676.7
  Bottom Layer w8: U9.3@4568.01,2360.98 4685.98,2360.98 4930,2605 6200.59,2605 6263.29,2667.7 7032.92,2667.7 7055.57,2645.05 U25.4@7055.57,2592.35
SDO0: U12.11 U25.8 | length 2774.8
  Bottom Layer w8: U12.11@4571.01,2898 4737,2898 4950,2685 6191.78,2685 6240.28,2733.5 7069.56,2733.5 7134.31,2668.75 U25.8@7134.31,2592.35
SDO1: U12.14 U25.5 | length 2658.2
  Bottom Layer w8: U12.14@4571.01,2748 4817,2748 4940,2625 6198.39,2625 6258.79,2685.4 7049.63,2685.4 7075.25,2659.78 U25.5@7075.25,2592.35
SDO2: U12.13 U25.6 | length 2698.2
  Bottom Layer w8: U12.13@4571.01,2798 4789.8,2798 4942.8,2645 6196.19,2645 6253.29,2702.1 7056.55,2702.1 7094.94,2663.71 U25.6@7094.94,2592.35
SDO3: U12.12 U25.7 | length 2736.5
  Bottom Layer w8: U12.12@4571.01,2848 4762,2848 4945,2665 6193.98,2665 6246.78,2717.8 7063.05,2717.8 7114.62,2666.23 U25.7@7114.62,2592.35
SRESETN: U5.3 U25.105 | length 2796.9
  Top Layer w8: v2@4700.7,1832.7 v2(4698,1830) 4716.6,1811.4 6260.21,1811.4 6505.61,1566 7055,1566 v2(7055.57,1566.57)
  Bottom Layer w8: U5.3@4568.02,1831.99 4570.01,1830 v2(4698,1830) ; v2(7055.57,1566.57) U25.105@7055.57,1761.65
STS0_LED: R227.1 U24.30 | length 185.4
  Bottom Layer w8: R227.1@3228,2878.5 3248.82,2857.68 3247.38,2856.24 U24.30@3247.38,2702.35
STS1_LED: R228.1 U24.28 | length 201.1
  Bottom Layer w8: R228.1@3155,2881.5 3208.01,2828.5 U24.28@3208.01,2702.35
STS2_LED: R229.1 U24.32 | length 213.6
  Bottom Layer w8: U24.32@3286.75,2702.35 3286.75,2798.25 R229.1@3370,2881.5
STS3_LED: R230.1 U24.31 | length 191.5
  Bottom Layer w8: U24.31@3267.06,2702.35 3267.06,2851.57 R230.1@3297,2881.5
SYS_5V: J2.7 J2.8 TP31.1 | length 206
  Top Layer w8: TP31.1@8134,1085 J2.7@8134,1191
  Bottom Layer w20: J2.7@8134,1191 J2.8@8134,1291
TCK: J19.4 R197.1 R201.2 | length 1392.3
  Top Layer w8: R201.2@5617.99,2113 5619.99,2115 J19.4@5718.5,2115 5785,2048.5 5785,1985 5875,1895 6760,1895 6822,1833 R197.1@6855.5,1833
TCK_ISO: J14.4 R117.1 R153.2 | length 1252.5
  Top Layer w8: J14.4@2515,3020 2517,3018 R153.2@2517,2936.5 2560,2893.5 2560,2660 2418.83,2518.83 2418.83,2066.17 2520,1965 R117.1@2598.5,1965
TDI: J19.2 R192.1 R202.2 | length 1350.9
  Top Layer w8: R202.2@5617.99,2314 5618.99,2315 J19.2@5718.5,2315 5878.5,2475 5922.6,2475 6070,2327.6 6537.6,2327.6 6590,2380 6590,2530.5 v2(6610,2550.5)
  Bottom Layer w8: v2(6610,2550.5) 6610.5,2551 R192.1@6660.5,2551
TDI_ISO: J14.2 R115.1 R155.2 | length 531
  Top Layer w8: R155.2@2309,2936.5 2309,3014 J14.2@2315,3020
  Bottom Layer w8: J14.2@2315,3020 2385,2950 2611.5,2950 R115.1@2696,2865.5
TDO: J19.3 R194.1 R203.2 | length 1933.1
  Top Layer w8: R203.2@5617.99,2211 5621.99,2215 J19.3@5718.5,2215 5805,2128.5 5805,1987.2 5877.9,1914.3 6435.35,1914.3 6436.05,1915 6785,1915 6820,1880 6985,1880 7020,1845 7020,1657 v2(6975,1612)
  Bottom Layer w8: v2(6975,1612) 6975.5,1611.5 R194.1@7016,1611.5
TDO_ISO: J14.3 R116.1 R157.2 | length 1334
  Top Layer w8: J14.3@2415,3020 2412,3017 R157.2@2412,2936.5 2455,2893.5 2455,2790 2530,2715 2530,2652.2 2397.14,2519.34 2397.14,2057.86 2555,1900 R116.1@2598.5,1900
TEST_0.2V: C64.1 J6.3 R96.2 | length 356.1
  Bottom Layer w20: R96.2@282.5,2290 282.5,2217.5 C64.1@291,2209 406,2209 472.5,2142.5 J6.3@472.5,2080
TEST_4.3V: C76.1 J9.1 R108.1 | length 364.7
  Bottom Layer w20: R108.1@285,2426.5 C76.1@285,2506 421,2506 474.5,2559.5 J9.1@474.5,2633
TMS: J19.1 R198.1 R211.2 | length 1356.2
  Top Layer w8: R211.2@5617.99,2416 5618.99,2415 5705,2415 J19.1@5711.75,2421.75 ; J19.1@5718.5,2415.7 J19.1@5718.5,2415 5796.29,2415 5871.99,2490.7 5929.3,2490.7 6076.7,2343.3 6528.3,2343.3 6574.3,2389.3 6574.3,2579.3 v2(6612,2617)
  Bottom Layer w8: v2@6613,2616 R198.1@6659.5,2616
  Bottom Layer w15: v2(6612,2617) v2@6613,2616
TMS_ISO: J14.1 R118.1 R159.2 | length 564.2
  Top Layer w8: J14.1@2215,3020 2218,3017 R159.2@2218,2936.5
  Bottom Layer w8: J14.1@2215,3020 2305,2930 2564.5,2930 R118.1@2630,2864.5
VCCO_0: C112.1 C113.1 C114.1 C115.1 C120.1 C121.1 C124.1 C125.1 C126.1 C127.1 J24.2 U24.119 U24.136 | length 712.2
  Top Layer w20: v1(2515,2170) 2520.5,2170 C121.1@2551,2139.5 2554.87,2135.62 C114.1@2607,2135.62 2611.38,2140 v1(2665,2140) 2669,2144 C112.1@2711.38,2144 C124.1@2711.38,2093 2711.38,2043 C125.1@2712.38,2042 ; C120.1@2559,2477.5 2564.87,2483.38 C113.1@2613,2483.38 2653.38,2483.38 v1(2670,2500) 2672,2502 C127.1@2706.38,2502 2706.38,2539.19 2705.38,2540.19 C115.1@2705.38,2605
  Bottom Layer w10: U24.119@2605.65,2139.36 2664.36,2139.36 v1(2665,2140) ; U24.136@2605.65,2474.01 2614.55,2474.01 2615.63,2475.09 2645.09,2475.09 v1(2670,2500)
VDD_3V3: J2.3 J2.4 TP30.1 | length 309
  Top Layer w20: TP30.1@8334,1082 J2.3@8334,1191 J2.4@8334,1291
  Bottom Layer w20: J2.3@8334,1191 J2.4@8334,1291
VDD_5V: J2.5 J2.6 L1.2 TP25.1 | length 277.3
  Top Layer w8: J2.5@8234,1191 8234,1089 TP25.1@8240,1083
  Top Layer w20: L1.2@8240,1016.22 TP25.1@8240,1083
  Bottom Layer w20: J2.5@8234,1191 J2.6@8234,1291
VDD_ADC: J2.32
VIN+: J8.1 R103.1 | length 285.9
  Bottom Layer w20: R103.1@391.5,2804 R103.1@392.5,2805
  Bottom Layer w40: J8.1@107,2804 R103.1@391.5,2804
VIN-: J7.1 R97.1 | length 289
  Bottom Layer w40: J7.1@107,1901 113,1895 R97.1@393.5,1895
WP: C78.2 J4.1 R246.1 U21.7 | length 1994.3
  Bottom Layer w8: J4.1@2070,720 2350,440 2970,440 3070,540 3070,1040 3093.62,1063.62 C78.2@3130,1063.62 3192.13,1063.62 R246.1@3200,1071.5 3280.19,1071.5 3330.8,1122.1 U21.7@3330.8,1164.19
WP1: C222.2 J21.1 R251.1 U28.7 | length 415.3
  Bottom Layer w8: J21.1@4980,2160 4983.62,2156.38 C222.2@5080,2156.38 5082.13,2158.5 R251.1@5140,2158.5 5140,2055 5165,2030 5215,2030 5227.7,2042.7 U28.7@5227.7,2088.81
X1_DONE: D6.2 R188.2 U25.73 | length 598.1
  Bottom Layer w8: U25.73@7685.49,1761.65 7685.49,1702.71 7764.03,1624.18 8095.19,1624.18 R188.2@8116.01,1645 8116.01,1700.5 D6.2@8107.5,1709
X1_INIT: R196.2 U25.67 | length 122.1
  Top Layer w8: v2(7823,1938) 7831.5,1929.5 R196.2@7872,1929.5
  Bottom Layer w8: U25.67@7756.35,1930.94 7815.94,1930.94 v2(7823,1938)
X1_M0: R181.2 U25.38 | length 230
  Top Layer w8: v2(7831,2502) 7908.5,2502 R181.2@7963.5,2557
  Bottom Layer w8: U25.38@7756.35,2501.8 7830.8,2501.8 v2(7831,2502)
X1_M1: R182.2 U25.37 | length 248.4
  Top Layer w8: v2(7831,2540) 7882.5,2540 R182.2@7963.5,2621
  Bottom Layer w8: U25.37@7756.35,2521.49 7812.49,2521.49 v2(7831,2540)
X1_M2: R183.2 U25.39 | length 228.3
  Top Layer w8: v2(7834,2462) 7932.5,2462 R183.2@7963.5,2493
  Bottom Layer w8: U25.39@7756.35,2482.12 7813.88,2482.12 v2(7834,2462)
X1_PROG_B: R191.2 U25.144 | length 175
  Top Layer w8: R191.2@6998.53,2592.35 7000,2590.88 v2(7000,2520) v2@7003.5,2523.5
  Bottom Layer w8: U25.144@6903.51,2521.49 6915,2521.49 6916.49,2520 v2(7000,2520)
X1_SUSPEND: R184.1 R185.2 U25.74 | length 629.4
  Bottom Layer w8: U25.74@7665.8,1761.65 7665.8,1700.2 7758,1608 8087,1608 8114,1581 R184.1@8118.5,1581 8118.5,1518 R185.2@8116.5,1516
X1_VS0: R216.2 R217.1 U25.45 | length 301.8
  Top Layer w8: v2(7845,2370) 7847,2370 7914,2303 R216.2@7963.5,2303 7963.5,2240 R217.1@7962.5,2239
  Bottom Layer w8: U25.45@7756.35,2364.01 7839.01,2364.01 v2(7845,2370)
X1_VS1: R214.2 U25.44 | length 230.1
  Top Layer w8: v2(7859,2403) 7867,2403 7903,2367 R214.2@7963.5,2367
  Bottom Layer w8: U25.44@7756.35,2383.69 7825.18,2383.69 7844.48,2403 v2(7859,2403)
X1_VS2: R218.2 U25.43 | length 237.1
  Top Layer w8: v2(7833,2426) 7838,2426 7858.3,2446.3 7914.7,2446.3 7931,2430 R218.2@7964.23,2430
  Bottom Layer w8: U25.43@7756.35,2403.38 7818.38,2403.38 7833,2418 v2(7833,2426)
X_DONE: D5.2 R120.2 U24.73 | length 463.5
  Bottom Layer w8: U24.73@3365.49,1871.65 3365.49,1698.51 3390.8,1673.2 R120.2@3390.8,1610.5 3457.01,1610.5 3489.5,1642.99 3489.5,1722.01 D5.2@3490,1722.5
X_INIT: R122.2 U24.67 | length 78.3
  Bottom Layer w8: U24.67@3436.35,2040.94 3505.56,2040.94 R122.2@3512,2034.5
X_M0: R154.2 U24.38 | length 365.6
  Bottom Layer w8: U24.38@3436.35,2611.8 3531.8,2611.8 3680.2,2760.2 R154.2@3680.2,2820.5
X_M1: R156.2 U24.37 | length 300.3
  Bottom Layer w8: U24.37@3436.35,2631.49 3494.29,2631.49 3618.2,2755.4 R156.2@3618.2,2822.5
X_M2: R158.2 U24.39 | length 432.2
  Bottom Layer w8: U24.39@3436.35,2592.12 3567.12,2592.12 3748.2,2773.2 R158.2@3748.2,2818.5
X_PROG_B: R121.2 U24.144 | length 186.3
  Bottom Layer w8: R121.2@2564,2800.5 2605.65,2758.86 U24.144@2605.65,2631.49
X_SUSPEND: R119.1 R165.2 U24.74 | length 338.8
  Bottom Layer w8: R165.2@3256.8,1609.5 3257.8,1610.5 R119.1@3325.8,1610.5 3325.8,1676.8 3345.8,1696.8 U24.74@3345.8,1871.65
X_VS0: R176.2 R177.1 U24.45 | length 752.5
  Bottom Layer w8: U24.45@3436.35,2474.01 3669.01,2474.01 3942.2,2747.2 R176.2@3942.2,2817.5 4004,2817.5 R177.1@4005,2818.5
X_VS1: R174.2 U24.44 | length 597.1
  Bottom Layer w8: U24.44@3436.35,2493.69 3588.69,2493.69 3878.2,2783.2 R174.2@3878.2,2818.5
X_VS2: R178.2 U24.43 | length 527.3
  Bottom Layer w8: U24.43@3436.35,2513.38 3548.38,2513.38 3814.2,2779.2 R178.2@3814.2,2818.5
pads on no net: FID1.1 FID2.1 FID3.1 FID4.1 FID5.1 FID6.1 FID7.1 FID8.1 H1.1 H2.1 H3.1 H4.1 H5. H6. H7. H8. H9.0 H10.0 H11.0 H12.0 H13. H14. H15. H16. H17.1 H18.1 H19.0 H20.0 H21.1 H30.0 J3.2 J3.3 J3.4 J3.5 J3.6 J3.7 J3.8 J3.9 J3.10 J3.11 J3.12 J3.13 J3.14 J3.15 J3.17 J3.19 J3.21 J3.23 J3.25 J3.26 J3.27 J3.29 J3.31 J3.33 J3.35 J3.36 J3.37 J3.39 J3.41 J3.43 J3.45 J3.46 J3.47 J3.48 J3.49 J3.51 J3.52 J3.53 J3.54 J3.55 J3.57 J3.MH1 J3.MH2 J18.2 J18.3 J18.4 J18.5 J18.6 J18.7 J18.8 J18.9 J18.10 J18.11 J18.12 J18.13 J18.14 J18.15 J18.17 J18.19 J18.21 J18.23 J18.25 J18.26 J18.27 J18.29 J18.31 J18.33 J18.35 J18.36 J18.37 J18.39 J18.41 J18.43 J18.45 J18.46 J18.47 J18.48 J18.49 J18.51 J18.52 J18.53 J18.54 J18.55 J18.57 J18.MH1 J18.MH2 LBL1.0 U1.6 U2.2 U2.17 U2.18 U2.19 U4.3 U4.4 U5.11 U6.3 U6.4 U7.2 U7.17 U7.18 U7.19 U8.3 U8.4 U10.3 U10.4 U11.3 U11.4 U13.2 U13.17 U13.18 U13.19 U16.1 U19.6 U22.1 U22.3 U22.5 U22.7 U22.8 U24.3 U24.4 U24.5 U24.6 U24.7 U24.8 U24.10 U24.11 U24.12 U24.13 U24.15 U24.16 U24.20 U24.21 U24.24 U24.25 U24.27 U24.29 U24.33 U24.35 U24.41 U24.42 U24.53 U24.54 U24.55 U24.59 U24.60 U24.62 U24.63 U24.64 U24.68 U24.78 U24.79 U24.80 U24.82 U24.83 U24.85 U24.87 U24.88 U24.96 U24.97 U24.98 U24.99 U24.102 U24.103 U24.105 U24.111 U24.112 U24.113 U24.114 U24.115 U24.116 U24.117 U24.120 U24.121 U24.123 U24.126 U24.127 U24.140 U24.142 U24.143 U25.33 U25.35 U25.41 U25.42 U25.53 U25.62 U25.80 U25.97 U25.123 U31.3 U36.1@2139.25,1257.17 U36.1@2170.75,1257.17 U36.2@2039.25,1257.17 U36.2@2070.75,1257.17 U36.3@1939.25,1257.17 U36.3@1970.75,1257.17 U36.4@1939.25,1402.83 U36.4@1970.75,1402.83 U36.5@2039.25,1402.83 U36.5@2070.75,1402.83 U36.6@2139.25,1402.83 U36.6@2170.75,1402.83 U37.4 U37.6 U37.9

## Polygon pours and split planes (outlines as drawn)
NetC2_1 on Bottom Layer "PWR-No Net" (solid, remove dead copper, pour order 88): 3753,3965 3750,3962 3750,3961 3750,3739 3650,3639 3650,3502 3600,3452 3592,3444 3592,3395 3592,3344 3604,3332 3747,3332 3849,3332 3883,3366 3883,3726 3841,3768 3841,3958 3834,3965
NetC62_1 on Bottom Layer "Top Layer-No Net" (solid, pour order 170): 1630,2552.84 1584.01,2552.84 1581.35,2550.18 1581.35,2378.65 1595,2365 1630,2365
5VDC on Bottom Layer "Top Layer-No Net" (solid, pour order 169): 5365,3710 5365,3615 5365,3515 5340,3490 4962,3490 4946,3506 4946,3701 4950,3705 5360,3705 5365,3700
AGND_ISO on Bottom Layer "Top Layer-No Net" (solid, pour order 115): 3120,3417 3315,3417 3323,3409 3323,3317 3311,3305 3077,3305 3052,3330 3052,3480 2979,3553 2979,3896 3330.21,3896 3345.72,3880.49 3345.72,3832.72 3340,3827 3333,3820 3208,3820 3078,3820 3065,3807 3060,3802 3060,3635 3060,3575 3068,3567 3119,3567 3148,3596 3197,3596 3198,3595 3198,3582 3196,3580 3156,3580 3135,3559 3105,3529 3105,3452 3105,3427 3115,3417
3P3V_ISO on Bottom Layer "Top Layer-No Net" (solid, pour order 109): 3339,3574 3596,3574 3610,3560 3610,3495 3595,3480 3260,3480 3245,3495 3245,3537 3250,3542 3327.42,3542 3334.94,3549.52 3334.94,3571.94 3337,3574
+12VDC on Bottom Layer "Top Layer-No Net" (solid, pour order 108): 5995,3471 5995,3432 6006,3421 6726,3421 6746,3441 6746,3616 6725,3637 6405,3637 6341,3701 6008,3701 5998,3691
+12VDC_IN on Bottom Layer "Top Layer-No Net" (solid, pour order 104): 6893,4114 6893,3481 6907,3467 7055,3467 7067,3479 7067,4139 7057,4149 6902,4149 6893,4140
GND on Bottom Layer "Top Layer-No Net" (solid, pour order 101): 6838,3711 6838,4124 6816,4146 5510,4146 5500,4136 5500,3777 5520,3757 6639,3757 6726,3670 6825,3670 6838,3683
NetC42_1 on Bottom Layer "Top Layer-No Net" (solid, pour order 95): 5737,3681 5737,3585 5730,3578 5687,3578 5664,3601 5579,3601 5570,3592 5570,3435 5559,3424 5514,3424 5499,3439 5499,3610 5488,3621 5397,3621 5388,3630 5388,3712 5399,3723 5726,3723 5737,3712
LDO_IN_ISO on Bottom Layer "Top Layer-No Net" (solid, pour order 106): 3367.18,3823.46 3367.18,3977.18 3373,3983 3446,3983 3453,3976 3454.18,3974.82 3454.18,3662.46 3451.18,3659.46 3336.18,3659.46 3333.18,3662.46 3333.18,3687.48 3331.19,3689.47 3305.17,3689.47 3302.18,3692.46 3302.18,3723.46 3304.18,3725.46 3360.18,3725.46 3367.18,3732.46 3367.18,3823.46
LDO_IN_ISO on Bottom Layer "Top Layer-No Net" (solid, pour order 99): 502,3978 502,3621 517,3606 522,3601 603,3601 608,3606 608,3609 608,3672 616,3680 616,3977 611,3982 506,3982 505,3981
LDO_IN_ISO on Bottom Layer "Top Layer-No Net" (solid, pour order 134): 3730,3974 3730,3780 3714,3764 3630,3764 3623,3771 3623,3777 3623,3871 3623,3910 3577,3956 502,3956 502,4068 518,4084 3716,4084 3730,4070
NetC2_1 on Bottom Layer "Top Layer-No Net" (solid, pour order 133): 3750,3962 3750,3739 3650,3639 3650,3373 3691,3332 3849,3332 3883,3366 3883,3726 3857,3752 3841,3768 3841,3958 3834,3965 3753,3965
